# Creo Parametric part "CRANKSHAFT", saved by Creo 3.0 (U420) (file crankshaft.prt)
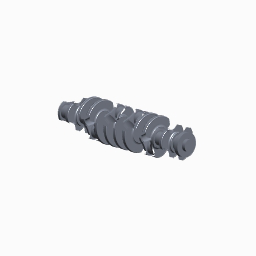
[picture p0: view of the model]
Units: millimeter Kilogram Sec (mmKs); MM, KILOGRAM, SECS

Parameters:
  MATERIAL = "35CrMo"

Created from: SHAFT.PRT

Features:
  1. datum plane "RIGHT"
  2. datum plane "TOP"
  3. datum plane "FRONT"
  4. coordinate system
  5. curve
  6. protrusion
  7. cut
  8. protrusion
  9. cut
  10. round
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
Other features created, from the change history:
  extrusion "Extrude 8"
  extrusion "Extrude 9"
  extrusion "Extrude 10"
  extrusion "Extrude 11"
  extrusion "Extrude 12"
  extrusion "Extrude 13"
  chamfer "Chamfer 1"
  hole "Hole 1"

Other named items: SHAFT_FROFILE, LOCAL_GROUP, LOCAL_GROUP_1, COPIED_GROUP, LOCAL_GROUP_2, LOCAL_GROUP_3, COPIED_GROUP_1, LOCAL_GROUP_4, LOCAL_GROUP_5, COPIED_GROUP_2, LOCAL_GROUP_6, LOCAL_GROUP_7, COPIED_GROUP_3, LOCAL_GROUP_8, LOCAL_GROUP_9, COPIED_GROUP_4, LOCAL_GROUP_10, LOCAL_GROUP_11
